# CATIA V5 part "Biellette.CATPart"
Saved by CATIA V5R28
Part number: Biellette
Bounding box of the stored display mesh (mm): x 0 to 48, y 0 to 16, z 0 to 12
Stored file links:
  C:\Users\8alex\Desktop\ECL\1A\PE\CATIA\Tuto\Biellette.CATPart
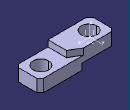
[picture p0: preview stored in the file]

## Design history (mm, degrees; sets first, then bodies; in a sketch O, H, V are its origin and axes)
AxisSystem1: origin (0, 0, 0), X (1, 0, 0), Y (0, 1, 0), Z (0, 0, 1)
Body1 (main body)
  Sketch1 on xy-plane, origin (0, 0, 0), H (1, 0, 0), V (0, 1, 0)
    line L1 (2.1213, 0) -> (45.8787, 0)
    line L2 (48, 2.1213) -> (48, 13.8787)
    line L3 (45.8787, 16) -> (2.1213, 16)
    line L4 (0, 13.8787) -> (0, 2.1213)
    point P1 (48, 0)
    point P2 (48, 16)
    point P3 (0, 16)
    circle A1 centre (39.5, 8) radius 5
    point P4 (39.5, 8)
    circle A2 centre (8.5, 8) radius 5
    point P5 (8.5, 8)
    line L5 (45.8787, 0) -> (48, 2.1213)
    line L6 (48, 13.8787) -> (45.8787, 16)
    line L7 (2.1213, 16) -> (0, 13.8787)
    line L8 (2.1213, 0) -> (0, 2.1213)
    radius A2 = 5
    radius A1 = 5
    distance P4 L2 = 8.5
    distance P4 P5 = 31
    distance P4 L3 = 8
    distance P5 L3 = 8
    distance P1 P2 = 16
    angle L1 L5 = 45
    length L5 = 3
    distance P2 P3 = 48
    angle L2 L6 = 45
    length L6 = 3
    angle L3 L7 = 45
    length L7 = 3
    angle L1 L8 = 45
    length L8 = 3
    horizontal: L1 H, L3 H
    vertical: L2 V, L4 V
    coincidence: L1 P1, L2 P1, L2 P2, L3 P2, L3 P3, L4 P3, L1 O, L4 O
  Pad1: profile Sketch1, direction (0, 0, 1), length 12
  Sketch2 on start face of Pad1, origin (0, 0, 0), H (1, 0, 0), V (0, -1, 0)
    line L1 (0, 0) -> (21, 0)
    line L2 (21, 0) -> (21, -20)
    line L3 (21, -20) -> (0, -20)
    line L4 (0, -20) -> (0, 0)
    reference projected line E1 (48, -2.1213) -> (48, -13.8787) from edge [start face of Pad1 | face of Pad1 from Sketch1.L2]
    distance L2 E1 = 27
    horizontal: L1 H, L3 H
    vertical: L2 V, L4 V
  Pocket1: profile Sketch2, direction (0, 0, 1), length 4
  Sketch3 on end face of Pad1, origin (0, 0, 12), H (1, 0, 0), V (0, 1, 0)
    point P1 (27, 0)
    line L1 (27, 0) -> (27, 12)
    line L2 (27, 12) -> (13.1436, 20)
    line L3 (13.1436, 20) -> (48, 20)
    line L4 (48, 20) -> (48, 0)
    line L5 (48, 0) -> (27, 0)
    reference projected line E1 (48, 2.1213) -> (48, 13.8787) from edge [face of Pad1 from Sketch1.L2 | end face of Pad1]
    reference projected line E2 (45.8787, 16) -> (2.1213, 16) from edge [face of Pad1 from Sketch1.L3 | end face of Pad1]
    distance L4 E1 = 0
    length L1 = 12
    angle L2 E2 = 30
    length L5 = 21
    coincidence: P1 H
    vertical: L1 V, L4 V
    horizontal: L3 H, L5 H
  Pocket2: profile Sketch3, direction (0, 0, -1), length 4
